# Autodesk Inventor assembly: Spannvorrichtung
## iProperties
Company: HERDT-Verlag
Created: 2006-01
Part Number: Spannvorrichtung
Document SubType Name: Assembly
Designer: Eichenseer
Project: Inventor 11 - Grundkurs
Checked By: G. Lehmann
Engr Approved By: M. Grouls
Engineer: Käs
Author: P. Tropf
Subject: Inventor 10 - Grundkurs
